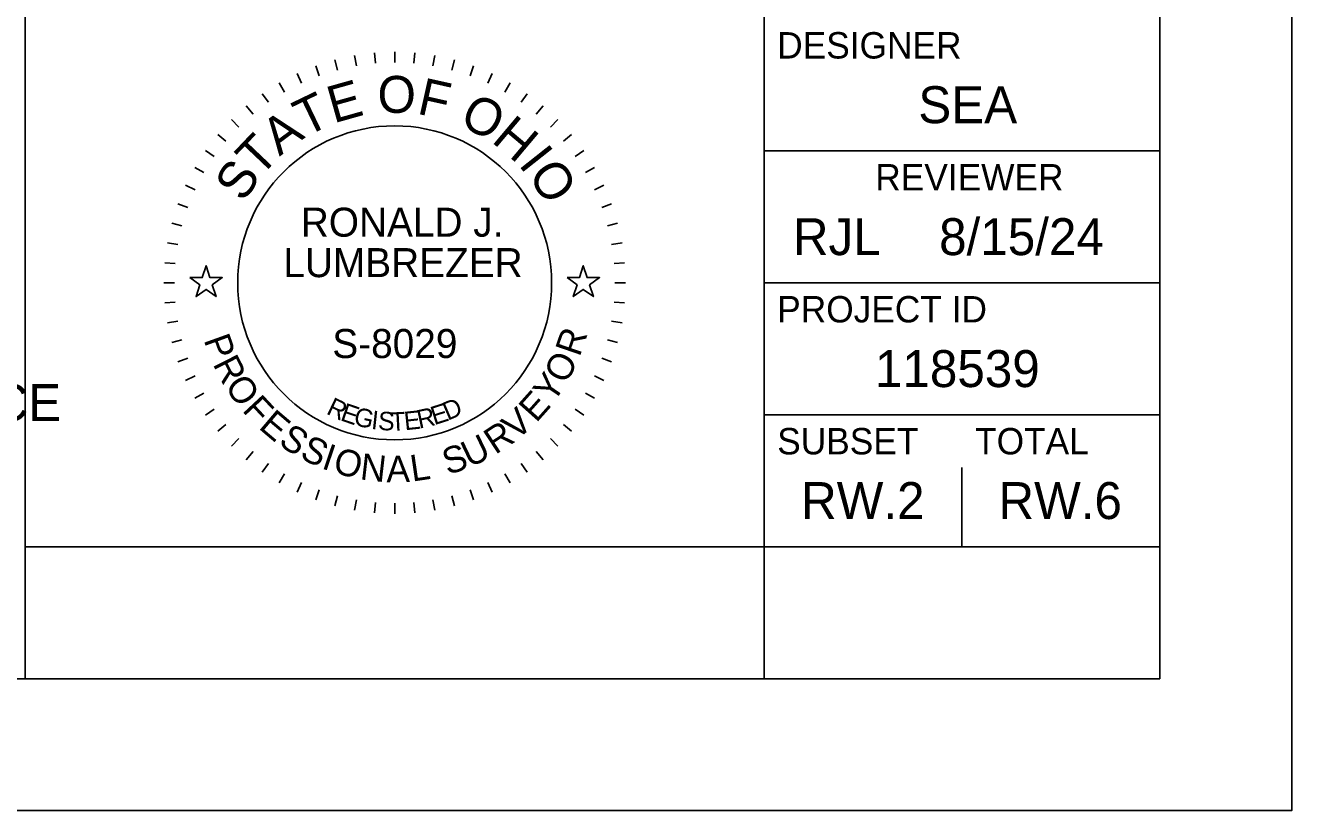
# Model space of a CAD drawing. Extents: x -4.7 to 34, y -3.1 to 22.
# Drawn here: x 29.2 to 34, y 0 to 2.976 of the extents above; entities that cross this region are included whole.
import ezdxf

# ---------------------------------------------------------------- set-up
doc = ezdxf.new("R2010")
doc.units = 0
for name, color, linetype in [('Default', 7, 'Continuous'), ('SC_Scratch2', 7, 'Continuous'), ('SH_Border', 7, 'Continuous'), ('SH_Cut_Line', 7, 'Continuous'), ('SH_Data', 7, 'Continuous')]:
    doc.layers.add(name, color=color, linetype=linetype)

msp = doc.modelspace()

# ---------------------------------------------------------------- linework, layer by layer
at = {"layer": 'Default'}
for points in [[(29.8236, 2.02), (29.8705, 2.02), (29.885, 2.0645), (29.8995, 2.02), (29.9464, 2.02), (29.9085, 1.9924), (29.923, 1.9478), (29.885, 1.9754), (29.847, 1.9478), (29.8615, 1.9924)], [(31.2536, 2.02), (31.3005, 2.02), (31.315, 2.0645), (31.3295, 2.02), (31.3764, 2.02), (31.3385, 1.9924), (31.353, 1.9478), (31.315, 1.9754), (31.277, 1.9478), (31.2915, 1.9924)]]:
    msp.add_lwpolyline(points, close=True, dxfattribs=at)
at = {"layer": 'SH_Border'}
for p, q in [((32, 0.5), (32, 21.5)), ((32, 2.5), (33.5, 2.5)), ((32, 2), (33.5, 2)), ((32, 1.5), (33.5, 1.5)), ((32, 1), (33.5, 1))]:
    msp.add_line(p, q, dxfattribs=at)
msp.add_lwpolyline([(1.5, 21.5), (33.5, 21.5), (33.5, 0.5), (1.5, 0.5)], close=True, dxfattribs=at)
at = {"layer": 'SH_Cut_Line'}
msp.add_lwpolyline([(0, 0), (34, 0), (34, 22), (0, 22)], close=True, dxfattribs=at)
at = {"layer": 'SH_Data'}
for p, q in [((29.2, 3.75), (29.2, 0.5)), ((30.3735, 2.8452), (30.3839, 2.8065)), ((30.4481, 2.8617), (30.455, 2.8223)), ((30.5237, 2.8717), (30.5272, 2.8318)), ((30.6, 2.875), (30.6, 2.835)), ((30.6763, 2.8717), (30.6728, 2.8318)), ((30.7519, 2.8617), (30.745, 2.8223)), ((30.8265, 2.8452), (30.8161, 2.8065)), ((30.2302, 2.793), (30.2471, 2.7568)), ((30.3007, 2.8222), (30.3144, 2.7846)), ((30.8993, 2.8222), (30.8856, 2.7846)), ((30.9698, 2.793), (30.9529, 2.7568)), ((30.1625, 2.7578), (30.1825, 2.7231)), ((31.0375, 2.7578), (31.0175, 2.7231)), ((30.0981, 2.7168), (30.1211, 2.684)), ((31.1019, 2.7168), (31.0789, 2.684)), ((30.0376, 2.6703), (30.0633, 2.6396)), ((31.1624, 2.6703), (31.1367, 2.6396)), ((29.9813, 2.6187), (30.0096, 2.5904)), ((31.2187, 2.6187), (31.1904, 2.5904)), ((29.9297, 2.5624), (29.9604, 2.5367)), ((31.2703, 2.5624), (31.2396, 2.5367)), ((29.8832, 2.5019), (29.916, 2.4789)), ((31.3168, 2.5019), (31.284, 2.4789)), ((29.8422, 2.4375), (29.8769, 2.4175)), ((31.3578, 2.4375), (31.3231, 2.4175)), ((29.807, 2.3698), (29.8432, 2.3529)), ((31.393, 2.3698), (31.3568, 2.3529)), ((29.7778, 2.2993), (29.8154, 2.2856)), ((31.4222, 2.2993), (31.3846, 2.2856)), ((29.7548, 2.2265), (29.7935, 2.2161)), ((31.4452, 2.2265), (31.4065, 2.2161)), ((29.7383, 2.1519), (29.7777, 2.145)), ((31.4617, 2.1519), (31.4223, 2.145)), ((29.7283, 2.0763), (29.7682, 2.0728)), ((31.4717, 2.0763), (31.4318, 2.0728)), ((29.725, 2), (29.765, 2)), ((31.475, 2), (31.435, 2)), ((29.7283, 1.9237), (29.7682, 1.9272)), ((31.4717, 1.9237), (31.4318, 1.9272)), ((29.7383, 1.8481), (29.7777, 1.855)), ((31.4617, 1.8481), (31.4223, 1.855)), ((29.7548, 1.7735), (29.7935, 1.7839)), ((31.4452, 1.7735), (31.4065, 1.7839)), ((29.7778, 1.7007), (29.8154, 1.7144)), ((31.4222, 1.7007), (31.3846, 1.7144)), ((29.807, 1.6302), (29.8432, 1.6471)), ((31.393, 1.6302), (31.3568, 1.6471)), ((29.8422, 1.5625), (29.8769, 1.5825)), ((31.3578, 1.5625), (31.3231, 1.5825)), ((29.8832, 1.4981), (29.916, 1.5211)), ((31.3168, 1.4981), (31.284, 1.5211)), ((29.9297, 1.4376), (29.9604, 1.4633)), ((31.2703, 1.4376), (31.2396, 1.4633)), ((29.9813, 1.3813), (30.0096, 1.4096)), ((31.2187, 1.3813), (31.1904, 1.4096)), ((30.0376, 1.3297), (30.0633, 1.3604)), ((31.1624, 1.3297), (31.1367, 1.3604)), ((30.0981, 1.2832), (30.1211, 1.316)), ((31.1019, 1.2832), (31.0789, 1.316)), ((32.75, 1), (32.75, 1.3)), ((30.1625, 1.2422), (30.1825, 1.2769)), ((31.0375, 1.2422), (31.0175, 1.2769)), ((30.2302, 1.207), (30.2471, 1.2432)), ((30.3007, 1.1778), (30.3144, 1.2154)), ((30.8993, 1.1778), (30.8856, 1.2154)), ((30.9698, 1.207), (30.9529, 1.2432)), ((30.3735, 1.1548), (30.3839, 1.1935)), ((30.4481, 1.1383), (30.455, 1.1777)), ((30.5237, 1.1283), (30.5272, 1.1682)), ((30.6, 1.125), (30.6, 1.165)), ((30.6763, 1.1283), (30.6728, 1.1682)), ((30.7519, 1.1383), (30.745, 1.1777)), ((30.8265, 1.1548), (30.8161, 1.1935))]:
    msp.add_line(p, q, dxfattribs=at)
msp.add_lwpolyline([(32, 0.5), (32, 1), (29.2, 1), (29.2, 0.5)], close=True, dxfattribs=at)
msp.add_circle((30.6, 2), 0.595, dxfattribs=at)

# ---------------------------------------------------------------- texts
at = {"layer": 'SC_Scratch2'}
msp.add_text("WOOD COUNTY RECORDER'S OFFICE", height=0.14, dxfattribs=at).set_placement((25.868, 1.4764))
at = {"layer": 'SH_Data'}
for s, height, p in [('DESIGNER', 0.1, (32.05, 2.85)), ('SEA', 0.14, (32.5848, 2.605)), ('REVIEWER', 0.1, (32.4218, 2.35)), ('RONALD J.', 0.11, (30.2441, 2.1749)), ('RJL', 0.14, (32.1095, 2.105)), ('8/15/24', 0.14, (32.6636, 2.105)), ('LUMBREZER', 0.11, (30.1779, 2.0216)), ('PROJECT ID', 0.1, (32.05, 1.85)), ('S-8029', 0.11, (30.3636, 1.7151)), ('118539', 0.14, (32.4204, 1.605)), ('SUBSET', 0.1, (32.05, 1.35)), ('TOTAL', 0.1, (32.8, 1.35)), ('RW.2', 0.14, (32.1404, 1.105)), ('RW.6', 0.14, (32.8886, 1.105))]:
    msp.add_text(s, height=height, dxfattribs=at).set_placement(p)
for s, height, rotation, p in [('O', 0.14, 359.7812, (30.5347, 2.6443)), ('E', 0.14, 15.7571, (30.3684, 2.6038)), ('F', 0.14, 347.4362, (30.6811, 2.6417)), ('T', 0.14, 25.7167, (30.2616, 2.5518)), ('O', 0.14, 332.2586, (30.8398, 2.6015)), ('A', 0.14, 36.4747, (30.1634, 2.4781)), ('H', 0.14, 319.9136, (30.9632, 2.5361)), ('T', 0.14, 46.4344, (30.0883, 2.3964)), ('I', 0.14, 308.367, (31.0665, 2.4483)), ('S', 0.14, 57.1924, (30.0281, 2.3014)), ('O', 0.14, 303.1491, (31.1021, 2.4089)), ('R', 0.1, 70.983, (31.3009, 1.7167)), ('P', 0.1, 289.7431, (29.8753, 1.7841)), ('R', 0.1, 296.9802, (29.9093, 1.6927)), ('O', 0.1, 62.7428, (31.2501, 1.6133)), ('O', 0.1, 304.7158, (29.9532, 1.6079)), ('Y', 0.1, 55.5058, (31.2, 1.54)), ('E', 0.1, 48.2687, (31.1366, 1.4673)), ('F', 0.1, 312.956, (30.0192, 1.5158)), ('R', 0.07, 334.487, (30.3375, 1.5051)), ('E', 0.07, 341.04, (30.3906, 1.4801)), ('E', 0.07, 17.6836, (30.7498, 1.4602)), ('D', 0.07, 23.3052, (30.801, 1.477)), ('E', 0.1, 319.6885, (30.0808, 1.4504)), ('G', 0.07, 347.4752, (30.4414, 1.4618)), ('I', 0.07, 353.7858, (30.5091, 1.4468)), ('S', 0.07, 356.8926, (30.5358, 1.4429)), ('T', 0.07, 3.0061, (30.5857, 1.4387)), ('E', 0.07, 6.0117, (30.6389, 1.4412)), ('R', 0.07, 11.9184, (30.6925, 1.4474)), ('V', 0.1, 41.0316, (31.0615, 1.4007)), ('S', 0.1, 326.9255, (30.1554, 1.3885)), ('R', 0.1, 33.296, (30.9815, 1.3473)), ('S', 0.1, 334.1626, (30.236, 1.3374)), ('U', 0.1, 25.5604, (30.8833, 1.2986)), ('I', 0.1, 341.3997, (30.3191, 1.2979)), ('O', 0.1, 345.1351, (30.3618, 1.2821)), ('N', 0.1, 353.3752, (30.466, 1.2555)), ('A', 0.1, 1.1108, (30.5692, 1.2443)), ('L', 0.1, 8.3479, (30.6664, 1.2467)), ('S', 0.1, 18.3234, (30.8005, 1.2711))]:
    msp.add_text(s, height=height, rotation=rotation, dxfattribs=at).set_placement(p)

doc.saveas('drawing.dxf')
